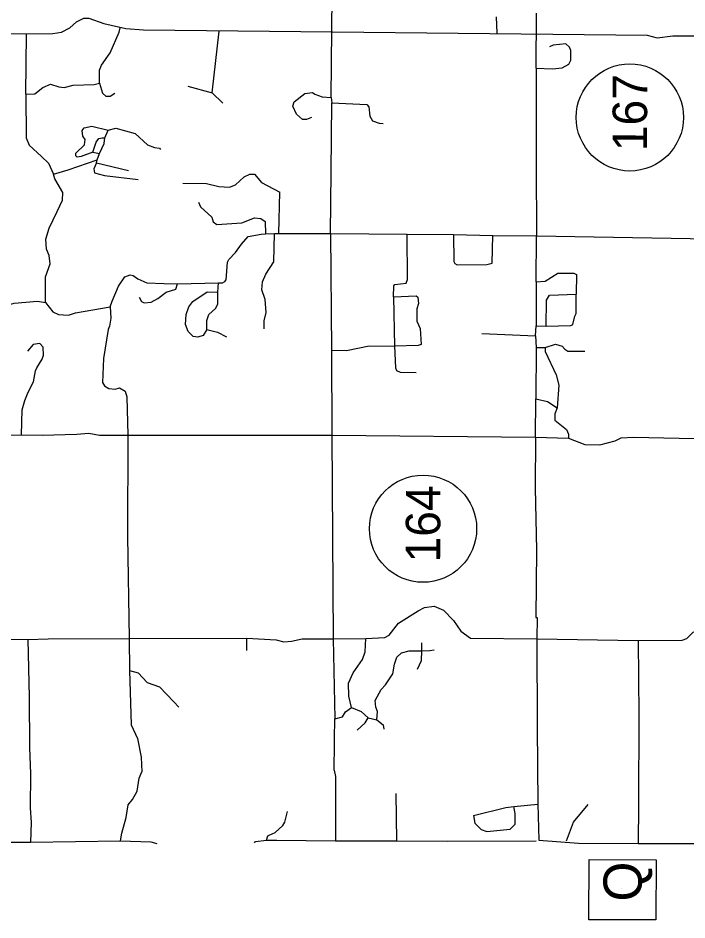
# Model space of a CAD drawing. Extents: x 299354 to 1325680, y 96128 to 228242.
# Drawn here: x 333137 to 350586, y 98300 to 121836 of the extents above; entities that cross this region are included whole.
import ezdxf

# ---------------------------------------------------------------- set-up
doc = ezdxf.new("R2010")
doc.units = 0
for name, color, linetype in [('Level 12', 7, 'Continuous'), ('Level 13', 7, 'Continuous'), ('Level 2', 7, 'Continuous'), ('Level 4', 7, 'Continuous')]:
    doc.layers.add(name, color=color, linetype=linetype)

msp = doc.modelspace()

# ---------------------------------------------------------------- linework, layer by layer
at = {"layer": 'Level 12'}
for p, q in [((349096, 119242), (349096, 119242)), ((343702, 108510), (343702, 108510))]:
    msp.add_line(p, q, dxfattribs=at)
for centre in [(349096, 119242), (343702, 108510)]:
    msp.add_circle(centre, 1398, dxfattribs=at)
at = {"layer": 'Level 13'}
msp.add_line((348883, 99122), (348883, 99122), dxfattribs=at)
msp.add_lwpolyline([(349776, 98300), (348026, 98307), (348033, 99877), (349783, 99870)], close=True, dxfattribs=at)
at = {"layer": 'Level 2'}
for points in [[(341305, 119759), (341371, 126825)], [(329011, 121428), (334049, 121433), (334274, 121464), (334492, 121579), (334660, 121736), (334853, 121834), (334986, 121833), (335377, 121696), (335951, 121566), (336410, 121528), (349544, 121393), (349810, 121323), (350219, 121370), (353997, 121369)], [(341304, 117825), (341321, 119625)], [(341305, 119759), (341321, 119625)], [(341289, 116217), (341304, 117825)], [(341289, 116217), (341311, 113167)], [(341311, 113167), (341324, 110950)], [(341324, 110950), (341359, 105633)], [(341359, 105633), (341398, 103549)], [(341392, 102907), (341393, 103024), (341398, 103549)], [(341385, 102207), (341392, 102907)], [(341385, 102207), (341417, 102041), (341414, 101699)], [(341414, 101699), (341418, 100365)], [(331077, 100334), (333462, 100329)], [(333462, 100329), (335806, 100366)], [(335806, 100366), (336598, 100342), (336758, 100292)], [(339306, 100316), (339333, 100351), (339617, 100382)], [(339617, 100382), (339892, 100379)], [(339892, 100379), (341418, 100365)], [(341418, 100365), (343011, 100368)], [(343011, 100368), (344346, 100356)], [(344346, 100356), (346656, 100368)], [(346723, 100384), (347756, 100308), (349316, 100294)], [(349316, 100294), (351042, 100295)]]:
    msp.add_lwpolyline(points, dxfattribs=at)
at = {"layer": 'Level 4'}
for points in [[(346650, 120527), (346663, 121960)], [(345612, 121870), (345624, 121445)], [(335263, 120138), (335266, 120472), (335317, 120605), (335537, 120928), (335775, 121467), (335801, 121584)], [(338204, 119887), (338386, 121494)], [(333342, 119847), (333356, 121422)], [(346650, 120527), (347075, 120515), (347334, 120537), (347502, 120636), (347553, 120736), (347555, 120985), (347523, 121077), (347423, 121162), (347098, 121131), (346997, 121082)], [(346650, 120527), (346656, 118017)], [(333342, 119847), (333575, 119862), (333785, 120027), (333986, 120108), (334202, 120040), (334344, 120022), (334578, 120086), (335120, 120106), (335263, 120138)], [(335263, 120138), (335344, 119879), (335426, 119795), (335543, 119794), (335660, 119876)], [(337564, 120059), (338204, 119887)], [(333342, 119847), (333348, 118714), (333430, 118522), (333752, 118219), (333934, 118050), (334065, 117758)], [(338204, 119887), (338477, 119618)], [(340792, 119238), (340658, 119190), (340558, 119190), (340401, 119325), (340303, 119534), (340337, 119651), (340614, 119865), (340815, 119896), (340881, 119846), (341072, 119777), (341305, 119759)], [(341321, 119625), (342238, 119584), (342287, 119516), (342318, 119275), (342384, 119157), (342559, 119089), (342659, 119088)], [(335087, 118340), (334786, 118226), (334678, 118210), (334645, 118244), (334645, 118311), (334872, 118525), (334890, 118667), (334824, 118751), (334809, 118901), (334860, 118967), (335060, 119015), (335485, 118911)], [(335400, 118712), (335485, 118911)], [(335485, 118911), (335685, 118960), (336193, 118822), (336515, 118527), (336698, 118459), (336823, 118441), (336856, 118407)], [(335087, 118340), (335173, 118598), (335249, 118697), (335333, 118713), (335400, 118712)], [(335262, 118305), (335381, 118562), (335400, 118712)], [(335087, 118340), (335262, 118305)], [(335202, 118139), (335262, 118305)], [(334065, 117758), (334441, 117871), (335202, 118139)], [(335185, 118056), (335117, 117898), (335133, 117798), (335390, 117729), (336273, 117621)], [(335185, 118056), (335202, 118139)], [(335185, 118056), (336017, 117857)], [(346656, 118017), (346660, 116152)], [(333850, 114409), (333856, 115084), (333976, 115425), (333945, 115642), (333880, 115809), (333866, 116068), (333952, 116350), (334156, 116790), (334300, 117080), (334302, 117280), (334097, 117641), (334065, 117758)], [(337440, 117527), (338049, 117521), (338373, 117444), (338657, 117424), (338808, 117481), (339035, 117696), (339185, 117761), (339302, 117760), (339492, 117542), (339965, 117296)], [(339938, 116213), (339965, 117296)], [(337844, 117032), (337893, 116906), (338191, 116637), (338223, 116520), (338323, 116452), (338974, 116496), (339308, 116627), (339467, 116609), (339583, 116524), (339596, 116207)], [(338367, 114927), (338467, 114926), (338534, 114959), (338568, 115008), (338605, 115466), (338639, 115533), (338808, 115715), (338968, 115938), (339137, 116137), (339480, 116200), (339596, 116207)], [(339557, 113724), (339559, 113933), (339611, 114149), (339581, 114491), (339499, 114742), (339518, 114950), (339603, 115149), (339806, 115472), (339830, 116214)], [(339596, 116207), (339830, 116214)], [(339830, 116214), (339938, 116213)], [(339938, 116213), (341289, 116217)], [(341289, 116217), (343291, 116199)], [(342934, 114560), (342937, 114852), (342970, 114885), (343262, 114916), (343297, 115016), (343291, 116199)], [(343291, 116199), (344492, 116188)], [(344492, 116188), (344502, 115480), (344535, 115429), (344593, 115395), (345369, 115405), (345502, 115437), (345526, 116162)], [(344492, 116188), (345526, 116162)], [(345526, 116162), (346660, 116152)], [(346649, 114952), (346660, 116152)], [(346660, 116152), (351171, 116078), (351371, 116076)], [(330840, 115395), (330872, 115178), (330971, 115044), (331311, 114849), (331544, 114780), (332092, 114542), (332574, 114363), (332866, 114343), (333033, 114392), (333642, 114445), (333850, 114409)], [(335542, 114302), (335594, 114444), (335756, 114842), (335925, 115082), (336059, 115131), (336142, 115114), (336266, 115029), (336499, 114927), (336941, 114906)], [(346649, 114952), (346891, 114966), (347218, 115180), (347635, 115176), (347701, 115142), (347697, 114634)], [(336295, 114554), (336361, 114437), (336427, 114403), (336611, 114418), (336787, 114516), (337005, 114681), (337256, 114762), (337299, 114903)], [(336941, 114906), (337299, 114903)], [(337299, 114903), (338367, 114927)], [(338348, 114685), (338367, 114927)], [(346649, 114952), (346655, 113802)], [(338064, 113705), (337962, 113555), (337828, 113507), (337703, 113524), (337571, 113659), (337506, 113835), (337525, 114101), (337594, 114300), (337695, 114441), (338073, 114688), (338348, 114685)], [(338064, 113705), (338066, 113946), (338117, 114096), (338286, 114261), (338345, 114369), (338348, 114685)], [(346913, 113799), (346919, 114474), (347004, 114607), (347697, 114634)], [(346913, 113799), (347556, 113810), (347606, 113843), (347658, 114059), (347692, 114126), (347697, 114634)], [(333850, 114409), (334048, 114166), (334189, 114098), (334456, 114079), (334640, 114144), (335542, 114302)], [(342934, 114560), (343526, 114588), (343568, 114555), (343583, 114388), (343540, 114247), (343537, 113930), (343627, 113738), (343656, 113321), (343573, 113288), (342955, 113277)], [(342934, 114560), (342955, 113277)], [(335542, 114302), (335556, 114002), (335521, 113794), (335487, 113711), (335363, 112954), (335341, 112329), (335390, 112237), (335506, 112169), (335673, 112151), (335781, 112184), (335931, 112099), (335979, 111948), (336003, 110948)], [(338064, 113705), (338338, 113635), (338571, 113517)], [(346636, 113544), (346655, 113802)], [(346655, 113802), (346913, 113799)], [(345235, 113606), (346636, 113544)], [(346636, 113544), (346650, 113243)], [(333226, 110957), (333249, 111615), (333318, 111856), (333403, 112072), (333539, 112345), (333592, 112628), (333626, 112711), (333770, 112935), (333804, 113035), (333790, 113252), (333707, 113344), (333532, 113321), (333380, 113139)], [(341311, 113167), (341703, 113163), (342297, 113283), (342955, 113277)], [(342955, 113277), (342983, 112710), (343008, 112643), (343107, 112592), (343524, 112588)], [(346650, 113243), (346646, 111902)], [(346650, 113243), (346891, 113241)], [(346891, 113241), (346890, 113133), (347177, 112522), (347241, 112255), (347202, 111663)], [(346891, 113241), (347159, 113322), (347334, 113271), (347400, 113195), (347483, 113144), (347925, 113140)], [(346636, 110902), (346646, 111902)], [(346646, 111902), (346945, 111832), (347202, 111663)], [(347202, 111663), (347142, 111506), (347141, 111339), (347447, 111095), (347496, 110977), (347495, 110877)], [(330916, 110911), (333226, 110957)], [(333226, 110957), (333768, 110952), (334669, 110977), (334986, 111007), (335261, 110955), (336003, 110948)], [(336003, 110948), (335996, 108306)], [(336003, 110948), (341324, 110950)], [(341324, 110950), (346636, 110902)], [(346636, 110902), (346624, 109577), (346659, 107952), (346643, 106193), (346676, 106193), (346671, 105635)], [(346636, 110902), (347495, 110877)], [(347495, 110877), (347919, 110707), (348311, 110703), (348712, 110800), (348871, 110882), (349188, 110895)], [(349188, 110895), (351973, 110837)], [(335996, 108306), (336038, 105648)], [(342209, 105642), (342702, 105671), (342819, 105736), (343064, 106042), (343575, 106371), (343743, 106453), (343994, 106492), (344234, 106382), (344499, 106113), (344688, 105836), (344937, 105650), (346671, 105635)], [(349314, 105594), (350465, 105600), (350583, 105649), (350751, 105814), (350843, 105847), (350993, 105829), (351109, 105795), (351316, 105609), (351808, 105588), (351892, 105604), (351943, 105704), (351979, 106028)], [(331009, 105627), (333394, 105622)], [(333394, 105622), (333919, 105634)], [(333394, 105622), (333430, 104113), (333435, 102804), (333462, 102113), (333453, 101229), (333483, 100846), (333462, 100329)], [(333919, 105634), (336038, 105648)], [(336038, 105648), (339107, 105653)], [(336038, 105648), (336047, 104814)], [(339104, 105328), (339107, 105653)], [(339107, 105653), (339874, 105613), (340074, 105561), (340274, 105576), (340550, 105640), (341359, 105633)], [(341359, 105633), (342209, 105642)], [(341834, 103845), (341770, 104137), (341757, 104479), (341876, 104745), (342121, 105101), (342189, 105300), (342209, 105642)], [(343666, 105320), (343668, 105529)], [(346671, 105635), (346683, 103335)], [(346671, 105635), (349314, 105594)], [(349314, 105594), (349330, 103644)], [(342498, 103522), (342517, 103739), (342468, 103856), (342453, 104031), (342606, 104313), (342724, 104437), (342910, 104719), (342954, 104977), (343022, 105159), (343140, 105275), (343341, 105323), (343666, 105320)], [(343561, 104846), (343664, 105070), (343666, 105320)], [(343666, 105320), (343883, 105335), (343991, 105351)], [(336047, 104814), (336084, 103389), (336256, 103037), (336351, 102545), (336364, 102170)], [(336047, 104814), (336271, 104746), (336503, 104493), (336827, 104382), (337199, 103995), (337331, 103853)], [(341398, 103549), (341598, 103597), (341683, 103730), (341834, 103845)], [(341834, 103845), (342092, 103743), (342274, 103574)], [(341987, 103252), (342189, 103442), (342274, 103574)], [(342274, 103574), (342498, 103522)], [(349330, 103644), (349325, 101294), (349316, 100294)], [(342498, 103522), (342664, 103388), (342680, 103279)], [(346683, 103335), (346698, 101318)], [(335806, 100366), (335841, 100566), (335961, 100973), (336014, 101306), (336124, 101447), (336243, 101662), (336296, 102004), (336364, 102170)], [(342989, 101601), (343011, 100368)], [(345019, 101025), (345050, 100824), (345216, 100664), (345365, 100613), (345975, 100674), (346101, 100798), (346104, 101081), (346072, 101257)], [(345019, 101025), (345863, 101234), (346072, 101257)], [(346072, 101257), (346698, 101318)], [(346698, 101318), (346723, 100384)], [(347447, 100366), (347624, 100850), (348013, 101315)], [(339844, 100580), (340046, 100761), (340097, 100852), (340166, 101135)], [(339617, 100382), (339652, 100498), (339685, 100515), (339844, 100580)]]:
    msp.add_lwpolyline(points, dxfattribs=at)

# ---------------------------------------------------------------- texts
at = {"layer": 'Level 12'}
for s, p in [('167', (349543, 118361)), ('164', (344148, 107630))]:
    msp.add_text(s, height=900, rotation=89.767, dxfattribs=at).set_placement(p)
at = {"layer": 'Level 13'}
msp.add_text('Q', height=1000, rotation=89.767, dxfattribs=at).set_placement((349407, 98780))

doc.saveas('drawing.dxf')
